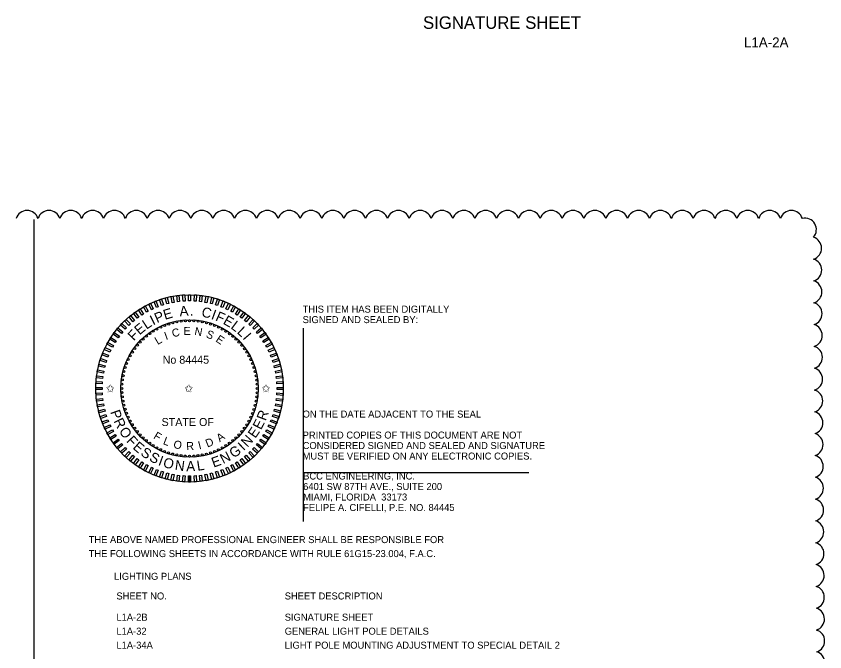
# Model space of a CAD drawing. Extents: x -811.2 to -795.1, y -2238.2 to -2204.
# Drawn here: x -803.27 to -795.18, y -2232.26 to -2225.9 of the extents above; entities that cross this region are included whole.
import ezdxf

# ---------------------------------------------------------------- set-up
doc = ezdxf.new("R2010")
doc.units = 0
for name, color, linetype in [('AdhocPoint_dp', 7, 'Continuous'), ('Cloud_dp', 7, 'Continuous'), ('PlotBorder_dp', 7, 'Continuous'), ('SheetLines_dp', 7, 'Continuous'), ('TextMinor', 7, 'Continuous'), ('TextMisc', 7, 'Continuous'), ('TextNotes', 7, 'Continuous'), ('TextShtNo', 7, 'Continuous')]:
    doc.layers.add(name, color=color, linetype=linetype)

msp = doc.modelspace()

# ---------------------------------------------------------------- linework, layer by layer
at = {"layer": 'AdhocPoint_dp'}
for p, q in [((-800.3974, -2229.0197), (-800.3974, -2230.9544)), ((-800.3974, -2230.4644), (-798.1407, -2230.4644))]:
    msp.add_line(p, q, dxfattribs=at)
at = {"layer": 'Cloud_dp'}
for centre, start, end in [((-803.1571, -2227.9569), 17.50004, 162.50004), ((-802.9388, -2227.9569), 17.5, 162.5), ((-802.7205, -2227.9569), 17.5, 162.5), ((-802.5022, -2227.9569), 17.5, 162.5), ((-802.2839, -2227.9569), 17.5, 162.5), ((-802.0655, -2227.9569), 17.5, 162.5), ((-801.8472, -2227.9569), 17.5, 162.5), ((-801.6289, -2227.9569), 17.5, 162.5), ((-801.4106, -2227.9569), 17.5, 162.5), ((-801.1922, -2227.9569), 17.5, 162.5), ((-800.9739, -2227.9569), 17.5, 162.5), ((-800.7556, -2227.9569), 17.5, 162.5), ((-800.5373, -2227.9569), 17.5, 162.5), ((-800.3189, -2227.9569), 17.5, 162.5), ((-800.1006, -2227.9569), 17.5, 162.5), ((-799.8823, -2227.9569), 17.5, 162.5), ((-799.664, -2227.9569), 17.5, 162.5), ((-799.4456, -2227.9569), 17.5, 162.5), ((-799.2273, -2227.9569), 17.5, 162.5), ((-799.009, -2227.9569), 17.5, 162.5), ((-798.7907, -2227.9569), 17.5, 162.5), ((-798.5724, -2227.9569), 17.5, 162.5), ((-798.354, -2227.9569), 17.5, 162.5), ((-798.1357, -2227.9569), 17.5, 162.5), ((-797.9174, -2227.9569), 17.5, 162.5), ((-797.6991, -2227.9569), 17.5, 162.5), ((-797.4807, -2227.9569), 17.5, 162.5), ((-797.2624, -2227.9569), 17.5, 162.5), ((-797.0441, -2227.9569), 17.5, 162.5), ((-796.8258, -2227.9569), 17.5, 162.5), ((-796.6074, -2227.9569), 17.5, 162.5), ((-796.3891, -2227.9569), 17.5, 162.5), ((-796.1708, -2227.9569), 17.5, 162.5), ((-795.9525, -2227.9569), 17.5, 162.5), ((-795.7341, -2227.9569), 17.5, 162.5), ((-795.5158, -2227.9569), 17.5, 162.5), ((-795.3807, -2228.034), 318.11161, 103.11161), ((-795.329, -2228.2198), 287.95289, 72.95289), ((-795.3273, -2228.4382), 287.95289, 72.95289), ((-795.3256, -2228.6565), 287.95289, 72.95289), ((-795.3239, -2228.8748), 287.95289, 72.95289), ((-795.3221, -2229.0931), 287.95289, 72.95289), ((-795.3204, -2229.3114), 287.95289, 72.95289), ((-795.3187, -2229.5297), 287.95289, 72.95289), ((-795.317, -2229.7481), 287.95289, 72.95289), ((-795.3152, -2229.9664), 287.95289, 72.95289), ((-795.3135, -2230.1847), 287.95289, 72.95289), ((-795.3118, -2230.403), 287.95289, 72.95289), ((-795.3101, -2230.6213), 287.95289, 72.95289), ((-795.3083, -2230.8396), 287.95289, 72.95289), ((-795.3066, -2231.058), 287.95289, 72.95289), ((-795.3049, -2231.2763), 287.95289, 72.95289), ((-795.3032, -2231.4946), 287.95289, 72.95289), ((-795.3014, -2231.7129), 287.95289, 72.95289), ((-795.2997, -2231.9312), 287.95289, 72.95289), ((-795.298, -2232.1495), 287.95289, 72.95289), ((-795.2963, -2232.3679), 287.95289, 72.95289)]:
    msp.add_arc(centre, 0.1145, start, end, dxfattribs=at)
at = {"layer": 'TextMinor'}
for radius in [0.9375, 0.6875]:
    msp.add_circle((-801.5329, -2229.6231), radius, dxfattribs=at)
at = {"layer": 'TextNotes'}
msp.add_line((-803.0858, -2237.5311), (-803.0858, -2227.9311), dxfattribs=at)
at = {"layer": 'TextShtNo'}
for p, q in [((-801.5429, -2230.5606), (-801.5431, -2230.4981)), ((-801.5329, -2230.5606), (-801.5331, -2230.4981)), ((-801.5229, -2230.5605), (-801.5231, -2230.498))]:
    msp.add_line(p, q, dxfattribs=at)
for points in [[(-801.7936, -2228.7877), (-801.8128, -2228.794), (-801.8321, -2228.7346), (-801.8129, -2228.7283)], [(-801.7407, -2228.773), (-801.7602, -2228.778), (-801.7757, -2228.7175), (-801.7562, -2228.7125)], [(-801.6869, -2228.7616), (-801.7067, -2228.7654), (-801.7184, -2228.7041), (-801.6986, -2228.7003)], [(-801.6325, -2228.7537), (-801.6525, -2228.7562), (-801.6603, -2228.6942), (-801.6403, -2228.6917)], [(-801.5777, -2228.7491), (-801.5978, -2228.7504), (-801.6018, -2228.6881), (-801.5816, -2228.6868)], [(-801.5227, -2228.748), (-801.5429, -2228.748), (-801.5429, -2228.6856), (-801.5227, -2228.6856)], [(-801.4678, -2228.7504), (-801.488, -2228.7491), (-801.484, -2228.6868), (-801.4639, -2228.6881)], [(-801.4131, -2228.7562), (-801.4332, -2228.7537), (-801.4253, -2228.6917), (-801.4053, -2228.6943)], [(-801.359, -2228.7655), (-801.3788, -2228.7617), (-801.3671, -2228.7003), (-801.3473, -2228.7041)], [(-801.3054, -2228.7781), (-801.325, -2228.773), (-801.3095, -2228.7126), (-801.2899, -2228.7176)], [(-801.2528, -2228.794), (-801.272, -2228.7878), (-801.2527, -2228.7284), (-801.2335, -2228.7346)], [(-801.9455, -2228.8514), (-801.9632, -2228.8611), (-801.9933, -2228.8064), (-801.9756, -2228.7967)], [(-801.8963, -2228.827), (-801.9145, -2228.8356), (-801.9411, -2228.7791), (-801.9229, -2228.7705)], [(-801.8456, -2228.8057), (-801.8643, -2228.8132), (-801.8873, -2228.7551), (-801.8686, -2228.7477)], [(-801.2013, -2228.8132), (-801.2201, -2228.8058), (-801.1971, -2228.7478), (-801.1783, -2228.7552)], [(-801.1511, -2228.8357), (-801.1694, -2228.8271), (-801.1428, -2228.7706), (-801.1246, -2228.7792)], [(-801.1024, -2228.8612), (-801.1201, -2228.8515), (-801.0901, -2228.7967), (-801.0724, -2228.8065)], [(-802.0828, -2228.9424), (-802.0984, -2228.9552), (-802.1382, -2228.9071), (-802.1226, -2228.8942)], [(-802.039, -2228.9092), (-802.0553, -2228.921), (-802.092, -2228.8705), (-802.0757, -2228.8587)], [(-801.9932, -2228.8788), (-802.0102, -2228.8896), (-802.0437, -2228.8369), (-802.0266, -2228.8261)], [(-801.0555, -2228.8897), (-801.0725, -2228.8789), (-801.039, -2228.8262), (-801.022, -2228.837)], [(-801.0104, -2228.9211), (-801.0267, -2228.9093), (-800.99, -2228.8588), (-800.9737, -2228.8706)], [(-800.9673, -2228.9553), (-800.9829, -2228.9425), (-800.9431, -2228.8944), (-800.9275, -2228.9072)], [(-802.1638, -2229.0166), (-802.1776, -2229.0314), (-802.2232, -2228.9886), (-802.2093, -2228.9739)], [(-802.1245, -2228.9782), (-802.1392, -2228.992), (-802.182, -2228.9465), (-802.1672, -2228.9327)], [(-800.9265, -2228.9922), (-800.9412, -2228.9784), (-800.8985, -2228.9328), (-800.8838, -2228.9467)], [(-800.8881, -2229.0315), (-800.9019, -2229.0168), (-800.8564, -2228.974), (-800.8426, -2228.9888)], [(-802.2007, -2229.0575), (-802.2135, -2229.073), (-802.2616, -2229.0332), (-802.2488, -2229.0177)], [(-800.8522, -2229.0732), (-800.8651, -2229.0576), (-800.817, -2229.0178), (-800.8041, -2229.0334)], [(-802.2663, -2229.1456), (-802.2771, -2229.1627), (-802.3298, -2229.1292), (-802.319, -2229.1122)], [(-802.2348, -2229.1005), (-802.2467, -2229.1168), (-802.2972, -2229.0801), (-802.2854, -2229.0638)], [(-800.819, -2229.117), (-800.8309, -2229.1007), (-800.7804, -2229.064), (-800.7685, -2229.0803)], [(-800.7887, -2229.1628), (-800.7995, -2229.1458), (-800.7467, -2229.1123), (-800.7359, -2229.1294)], [(-802.3203, -2229.2413), (-802.3289, -2229.2596), (-802.3854, -2229.233), (-802.3768, -2229.2147)], [(-802.2948, -2229.1926), (-802.3045, -2229.2103), (-802.3593, -2229.1802), (-802.3495, -2229.1625)], [(-800.7612, -2229.2105), (-800.7709, -2229.1928), (-800.7162, -2229.1627), (-800.7065, -2229.1804)], [(-800.7368, -2229.2597), (-800.7454, -2229.2415), (-800.6889, -2229.2149), (-800.6803, -2229.2331)], [(-802.3428, -2229.2915), (-802.3502, -2229.3103), (-802.4082, -2229.2873), (-802.4008, -2229.2685)], [(-800.7156, -2229.3104), (-800.723, -2229.2917), (-800.665, -2229.2687), (-800.6575, -2229.2874)], [(-802.3779, -2229.3956), (-802.3829, -2229.4151), (-802.4434, -2229.3996), (-802.4384, -2229.3801)], [(-802.362, -2229.343), (-802.3682, -2229.3622), (-802.4276, -2229.3429), (-802.4214, -2229.3237)], [(-800.6976, -2229.3624), (-800.7038, -2229.3432), (-800.6444, -2229.3239), (-800.6382, -2229.3431)], [(-800.6828, -2229.4153), (-800.6879, -2229.3958), (-800.6274, -2229.3802), (-800.6224, -2229.3998)], [(-802.3905, -2229.4491), (-802.3943, -2229.4689), (-802.4557, -2229.4572), (-802.4519, -2229.4374)], [(-800.6715, -2229.4691), (-800.6753, -2229.4493), (-800.6139, -2229.4376), (-800.6101, -2229.4574)], [(-802.3998, -2229.5033), (-802.4023, -2229.5233), (-802.4643, -2229.5155), (-802.4617, -2229.4955)], [(-800.6635, -2229.5235), (-800.666, -2229.5035), (-800.6041, -2229.4957), (-800.6016, -2229.5157)], [(-802.408, -2229.6129), (-802.408, -2229.6331), (-802.4704, -2229.6331), (-802.4704, -2229.6129)], [(-802.4056, -2229.558), (-802.4069, -2229.5781), (-802.4692, -2229.5742), (-802.4679, -2229.554)], [(-800.659, -2229.5783), (-800.6602, -2229.5581), (-800.5979, -2229.5542), (-800.5967, -2229.5744)], [(-800.6579, -2229.6333), (-800.6579, -2229.6131), (-800.5955, -2229.6131), (-800.5955, -2229.6333)], [(-802.4069, -2229.6679), (-802.4056, -2229.688), (-802.4679, -2229.6919), (-802.4692, -2229.6718)], [(-800.6603, -2229.6882), (-800.659, -2229.668), (-800.5967, -2229.672), (-800.5979, -2229.6921)], [(-802.4023, -2229.7226), (-802.3998, -2229.7427), (-802.4617, -2229.7505), (-802.4643, -2229.7305)], [(-802.3944, -2229.777), (-802.3906, -2229.7969), (-802.4519, -2229.8086), (-802.4557, -2229.7887)], [(-800.6753, -2229.797), (-800.6715, -2229.7772), (-800.6102, -2229.7889), (-800.614, -2229.8087)], [(-800.6661, -2229.7428), (-800.6635, -2229.7228), (-800.6016, -2229.7306), (-800.6041, -2229.7507)], [(-802.383, -2229.8308), (-802.378, -2229.8504), (-802.4385, -2229.8659), (-802.4435, -2229.8463)], [(-800.6879, -2229.8506), (-800.6829, -2229.831), (-800.6224, -2229.8465), (-800.6274, -2229.8661)], [(-802.3683, -2229.8838), (-802.362, -2229.903), (-802.4214, -2229.9223), (-802.4277, -2229.9031)], [(-802.3503, -2229.9357), (-802.3428, -2229.9545), (-802.4009, -2229.9775), (-802.4083, -2229.9587)], [(-800.7231, -2229.9547), (-800.7157, -2229.9359), (-800.6576, -2229.9589), (-800.665, -2229.9776)], [(-800.7039, -2229.9032), (-800.6976, -2229.884), (-800.6382, -2229.9033), (-800.6445, -2229.9225)], [(-802.329, -2229.9864), (-802.3204, -2230.0047), (-802.3769, -2230.0313), (-802.3855, -2230.013)], [(-800.7455, -2230.0049), (-800.7369, -2229.9866), (-800.6804, -2230.0132), (-800.689, -2230.0314)], [(-802.3046, -2230.0357), (-802.2949, -2230.0534), (-802.3496, -2230.0835), (-802.3593, -2230.0658)], [(-802.2772, -2230.0833), (-802.2664, -2230.1004), (-802.3191, -2230.1338), (-802.3299, -2230.1168)], [(-800.7996, -2230.1005), (-800.7888, -2230.0835), (-800.736, -2230.117), (-800.7468, -2230.134)], [(-800.771, -2230.0535), (-800.7613, -2230.0359), (-800.7066, -2230.0659), (-800.7163, -2230.0836)], [(-802.2468, -2230.1292), (-802.235, -2230.1455), (-802.2855, -2230.1822), (-802.2973, -2230.1659)], [(-802.2136, -2230.173), (-802.2008, -2230.1885), (-802.2489, -2230.2283), (-802.2617, -2230.2128)], [(-800.8652, -2230.1887), (-800.8523, -2230.1731), (-800.8042, -2230.2129), (-800.8171, -2230.2285)], [(-800.831, -2230.1456), (-800.8191, -2230.1293), (-800.7686, -2230.166), (-800.7805, -2230.1823)], [(-802.1778, -2230.2146), (-802.1639, -2230.2294), (-802.2095, -2230.2721), (-802.2233, -2230.2574)], [(-802.1393, -2230.254), (-802.1246, -2230.2678), (-802.1674, -2230.3133), (-802.1821, -2230.2995)], [(-800.9413, -2230.2679), (-800.9266, -2230.2541), (-800.8839, -2230.2996), (-800.8986, -2230.3134)], [(-800.902, -2230.2295), (-800.8882, -2230.2148), (-800.8427, -2230.2575), (-800.8565, -2230.2722)], [(-802.0985, -2230.2908), (-802.083, -2230.3037), (-802.1228, -2230.3518), (-802.1383, -2230.3389)], [(-802.0555, -2230.325), (-802.0392, -2230.3369), (-802.0759, -2230.3874), (-802.0922, -2230.3755)], [(-801.0268, -2230.337), (-801.0105, -2230.3251), (-800.9738, -2230.3756), (-800.9901, -2230.3875)], [(-800.983, -2230.3038), (-800.9675, -2230.2909), (-800.9277, -2230.339), (-800.9432, -2230.3519)], [(-802.0104, -2230.3564), (-801.9933, -2230.3672), (-802.0268, -2230.42), (-802.0438, -2230.4091)], [(-801.9634, -2230.385), (-801.9457, -2230.3947), (-801.9758, -2230.4494), (-801.9935, -2230.4397)], [(-801.9147, -2230.4105), (-801.8964, -2230.4191), (-801.923, -2230.4756), (-801.9413, -2230.467)], [(-801.8645, -2230.4329), (-801.8457, -2230.4403), (-801.8687, -2230.4984), (-801.8875, -2230.491)], [(-801.2203, -2230.4404), (-801.2015, -2230.433), (-801.1785, -2230.491), (-801.1973, -2230.4985)], [(-801.1696, -2230.4192), (-801.1513, -2230.4106), (-801.1247, -2230.4671), (-801.143, -2230.4757)], [(-801.1203, -2230.3948), (-801.1026, -2230.3851), (-801.0725, -2230.4398), (-801.0902, -2230.4495)], [(-801.0727, -2230.3673), (-801.0556, -2230.3565), (-801.0222, -2230.4092), (-801.0392, -2230.4201)], [(-801.813, -2230.4521), (-801.7938, -2230.4584), (-801.8131, -2230.5178), (-801.8323, -2230.5115)], [(-801.7604, -2230.4681), (-801.7408, -2230.4731), (-801.7564, -2230.5336), (-801.7759, -2230.5286)], [(-801.7069, -2230.4807), (-801.6871, -2230.4845), (-801.6988, -2230.5458), (-801.7186, -2230.542)], [(-801.6527, -2230.4899), (-801.6327, -2230.4925), (-801.6405, -2230.5544), (-801.6605, -2230.5519)], [(-801.598, -2230.4957), (-801.5779, -2230.497), (-801.5818, -2230.5593), (-801.602, -2230.5581)], [(-801.5431, -2230.4981), (-801.5229, -2230.4981), (-801.5229, -2230.5605), (-801.5431, -2230.5605)], [(-801.4881, -2230.497), (-801.468, -2230.4957), (-801.4641, -2230.5581), (-801.4842, -2230.5593)], [(-801.4334, -2230.4925), (-801.4133, -2230.4899), (-801.4055, -2230.5519), (-801.4255, -2230.5544)], [(-801.379, -2230.4845), (-801.3591, -2230.4807), (-801.3474, -2230.5421), (-801.3673, -2230.5458)], [(-801.3252, -2230.4731), (-801.3056, -2230.4681), (-801.2901, -2230.5286), (-801.3096, -2230.5336)], [(-801.2722, -2230.4584), (-801.253, -2230.4522), (-801.2337, -2230.5116), (-801.2529, -2230.5178)]]:
    msp.add_lwpolyline(points, close=True, dxfattribs=at)
for centre in [(-801.7417, -2228.9786), (-801.7009, -2228.9667), (-801.6593, -2228.9575), (-801.6173, -2228.9509), (-801.5749, -2228.9469), (-801.5324, -2228.9456), (-801.4898, -2228.947), (-801.4475, -2228.951), (-801.4054, -2228.9577), (-801.3639, -2228.967), (-801.323, -2228.9789), (-801.8955, -2229.0508), (-801.8588, -2229.0291), (-801.8209, -2229.0098), (-801.7818, -2228.993), (-801.283, -2228.9934), (-801.244, -2229.0103), (-801.2061, -2229.0297), (-801.1694, -2229.0514), (-801.9963, -2229.1288), (-801.9643, -2229.1007), (-801.9307, -2229.0747), (-801.1343, -2229.0753), (-801.1007, -2229.1014), (-801.0688, -2229.1296), (-802.0807, -2229.2244), (-802.0546, -2229.1908), (-802.0264, -2229.1589), (-801.0387, -2229.1597), (-801.0106, -2229.1917), (-800.9845, -2229.2253), (-802.1263, -2229.2962), (-802.1046, -2229.2596), (-800.9606, -2229.2605), (-800.939, -2229.2972), (-802.1626, -2229.3732), (-802.1457, -2229.3341), (-800.9197, -2229.3351), (-800.9028, -2229.3742), (-802.189, -2229.454), (-802.1771, -2229.4132), (-800.8884, -2229.4143), (-800.8766, -2229.4551), (-802.205, -2229.5376), (-802.1983, -2229.4956), (-800.8673, -2229.4967), (-800.8607, -2229.5387), (-802.2104, -2229.6225), (-802.209, -2229.58), (-800.8568, -2229.5811), (-800.8555, -2229.6236), (-802.2091, -2229.665), (-802.2051, -2229.7074), (-800.8609, -2229.7085), (-800.8568, -2229.6662), (-802.1985, -2229.7495), (-802.1892, -2229.791), (-800.8769, -2229.7921), (-800.8676, -2229.7506), (-802.1774, -2229.8319), (-802.163, -2229.8719), (-800.9032, -2229.873), (-800.8888, -2229.833), (-802.1462, -2229.911), (-802.1269, -2229.949), (-800.9395, -2229.9499), (-800.9202, -2229.912), (-802.1052, -2229.9856), (-802.0813, -2230.0208), (-800.9852, -2230.0217), (-800.9612, -2229.9866), (-802.0553, -2230.0545), (-802.0272, -2230.0864), (-801.9971, -2230.1165), (-801.0696, -2230.1173), (-801.0395, -2230.0872), (-801.0113, -2230.0553), (-801.9652, -2230.1447), (-801.9316, -2230.1708), (-801.8964, -2230.1948), (-801.1704, -2230.1954), (-801.1352, -2230.1715), (-801.1015, -2230.1454), (-801.8598, -2230.2165), (-801.8219, -2230.2358), (-801.7828, -2230.2528), (-801.7428, -2230.2672), (-801.7019, -2230.2791), (-801.365, -2230.2794), (-801.3241, -2230.2676), (-801.2841, -2230.2532), (-801.245, -2230.2363), (-801.207, -2230.217), (-801.6604, -2230.2884), (-801.6184, -2230.2951), (-801.576, -2230.2992), (-801.5329, -2230.3006), (-801.4909, -2230.2992), (-801.4486, -2230.2953), (-801.4065, -2230.2886)]:
    msp.add_circle(centre, 0.01, dxfattribs=at)

# ---------------------------------------------------------------- texts
at = {"layer": 'PlotBorder_dp'}
for s, height, p in [('       SIGNATURE SHEET         ', 0.125, (-799.5241, -2226.0251)), ('THIS ITEM HAS BEEN DIGITALLY', 0.07, (-800.4024, -2228.8645)), ('SIGNED AND SEALED BY:', 0.07, (-800.4024, -2228.9695)), ('ON THE DATE ADJACENT TO THE SEAL', 0.07, (-800.4024, -2229.9145)), ('PRINTED COPIES OF THIS DOCUMENT ARE NOT ', 0.07, (-800.4024, -2230.1245)), ('CONSIDERED SIGNED AND SEALED AND SIGNATURE ', 0.07, (-800.4024, -2230.2295)), ('MUST BE VERIFIED ON ANY ELECTRONIC COPIES.', 0.07, (-800.4024, -2230.3345)), ('BCC ENGINEERING, INC.', 0.07, (-800.3974, -2230.5344)), ('6401 SW 87TH AVE., SUITE 200', 0.07, (-800.3974, -2230.6394)), ('MIAMI, FLORIDA  33173', 0.07, (-800.3974, -2230.7444)), ('FELIPE A. CIFELLI, P.E. NO. 84445', 0.07, (-800.3974, -2230.8494)), ('THE ABOVE NAMED PROFESSIONAL ENGINEER SHALL BE RESPONSIBLE FOR ', 0.07, (-802.5415, -2231.1705)), ('THE FOLLOWING SHEETS IN ACCORDANCE WITH RULE 61G15-23.004, F.A.C.', 0.07, (-802.5415, -2231.3105)), ('LIGHTING PLANS', 0.07, (-802.2878, -2231.5376))]:
    msp.add_text(s, height=height, dxfattribs=at).set_placement(p)
at = {"layer": 'SheetLines_dp'}
msp.add_text('L1A-2A', height=0.1, dxfattribs=at).set_placement((-795.9908, -2226.2108))
at = {"layer": 'TextMisc'}
for s, p in [('SHEET NO.', (-802.2643, -2231.7345)), ('SHEET DESCRIPTION', (-800.5815, -2231.7345)), ('L1A-2B', (-802.2643, -2231.9467)), ('SIGNATURE SHEET', (-800.5815, -2231.9467)), ('L1A-32', (-802.2643, -2232.0867)), ('GENERAL LIGHT POLE DETAILS', (-800.5815, -2232.0867)), ('L1A-34A', (-802.2643, -2232.2267)), ('LIGHT POLE MOUNTING ADJUSTMENT TO SPECIAL DETAIL 2', (-800.5815, -2232.2267))]:
    msp.add_text(s, height=0.07, dxfattribs=at).set_placement(p)
at = {"layer": 'TextShtNo'}
for s, height, rotation, p in [('E', 0.1, 16.54261, (-801.7793, -2228.9373)), ('A', 0.1, 4.42103, (-801.6298, -2228.9009)), ('C', 0.1, 347.7999, (-801.4192, -2228.9033)), ('I', 0.1, 26.81606, (-801.8977, -2228.9923)), ('P', 0.1, 23.28287, (-801.8581, -2228.971)), ('.', 0.1, 356.65403, (-801.5313, -2228.8944)), ('I', 0.1, 340.0631, (-801.3234, -2228.9252)), ('F', 0.1, 336.52991, (-801.2807, -2228.9395)), ('E', 0.1, 330.07956, (-801.2055, -2228.9721)), ('E', 0.1, 40.12142, (-802.033, -2229.0932)), ('L', 0.1, 33.07918, (-801.9643, -2229.0358)), ('L', 0.1, 323.03732, (-801.1282, -2229.0172)), ('F', 0.1, 46.57177, (-802.0894, -2229.1527)), ('I', 0.08, 20.01168, (-801.7686, -2229.139)), ('C', 0.08, 12.20255, (-801.7007, -2229.1115)), ('E', 0.08, 0.41861, (-801.5926, -2229.088)), ('N', 0.08, 349.29143, (-801.4883, -2229.0865)), ('S', 0.08, 337.02207, (-801.3753, -2229.1083)), ('L', 0.1, 316.7742, (-801.0645, -2229.0649)), ('L', 0.08, 30.40215, (-801.8521, -2229.1895)), ('E', 0.08, 325.86633, (-801.2786, -2229.1485)), ('I', 0.1, 310.51108, (-801.0064, -2229.1194)), ('P', 0.1, 289.40551, (-802.3276, -2229.8577)), ('R', 0.1, 69.5134, (-800.7727, -2229.9528)), ('R', 0.1, 296.14576, (-802.2946, -2229.9493)), ('E', 0.1, 62.47116, (-800.8189, -2230.0435)), ('O', 0.1, 303.96711, (-802.2431, -2230.0499)), ('E', 0.1, 55.42892, (-800.8758, -2230.1279)), ('F', 0.1, 312.62798, (-802.1707, -2230.152)), ('F', 0.08, 328.72408, (-801.901, -2230.1197)), ('L', 0.08, 339.29159, (-801.8037, -2230.1787)), ('A', 0.08, 34.49917, (-801.2311, -2230.1625)), ('N', 0.1, 47.17876, (-800.9551, -2230.2169)), ('E', 0.1, 319.07833, (-802.1073, -2230.2203)), ('O', 0.08, 349.68206, (-801.699, -2230.2185)), ('R', 0.08, 2.33977, (-801.5645, -2230.2404)), ('I', 0.08, 14.20366, (-801.4369, -2230.2337)), ('D', 0.08, 22.01279, (-801.3548, -2230.215)), ('I', 0.1, 43.64556, (-800.9928, -2230.2514)), ('S', 0.1, 326.12056, (-802.0297, -2230.2862)), ('S', 0.1, 333.193, (-801.9443, -2230.3423)), ('N', 0.1, 26.86136, (-801.1972, -2230.3806)), ('G', 0.1, 35.11153, (-801.092, -2230.3246)), ('I', 0.1, 340.26543, (-801.8526, -2230.3875)), ('O', 0.1, 343.79863, (-801.8049, -2230.4058)), ('N', 0.1, 352.45949, (-801.6839, -2230.4378)), ('A', 0.1, 0.70966, (-801.5655, -2230.451)), ('L', 0.1, 8.47665, (-801.4533, -2230.4478)), ('E', 0.1, 19.81912, (-801.2926, -2230.4161))]:
    msp.add_text(s, height=height, rotation=rotation, dxfattribs=at).set_placement(p)
for s, p in [('No 84445', (-801.8019, -2229.3758)), ('✩', (-802.3679, -2229.661)), ('✩', (-801.5832, -2229.661)), ('✩', (-800.8113, -2229.661)), ('STATE OF', (-801.8126, -2229.9993))]:
    msp.add_text(s, height=0.08, dxfattribs=at).set_placement(p)

doc.saveas('drawing.dxf')
